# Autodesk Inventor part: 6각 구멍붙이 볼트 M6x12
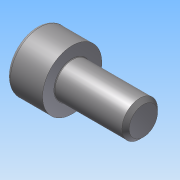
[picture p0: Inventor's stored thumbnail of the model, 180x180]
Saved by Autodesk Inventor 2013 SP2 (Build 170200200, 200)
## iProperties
Created: 2025-09
Part Number: 6각 구멍붙이 볼트 M6x12
Material: Generic
Document SubType Name: Modeling
Designer: a
Density: 1 g/cm^3
Author: a
변환 표준: STEP AP214IS
전처리기: Build: 200, Release: 2013 SP2 Update 6 - Date: Thu 07/17/2014
전송 단위: 밀리미터
불확실성: 0.01
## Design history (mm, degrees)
node "6각 구멍붙이 볼트 M6x121"
body "Solid1"
node "기준1"
